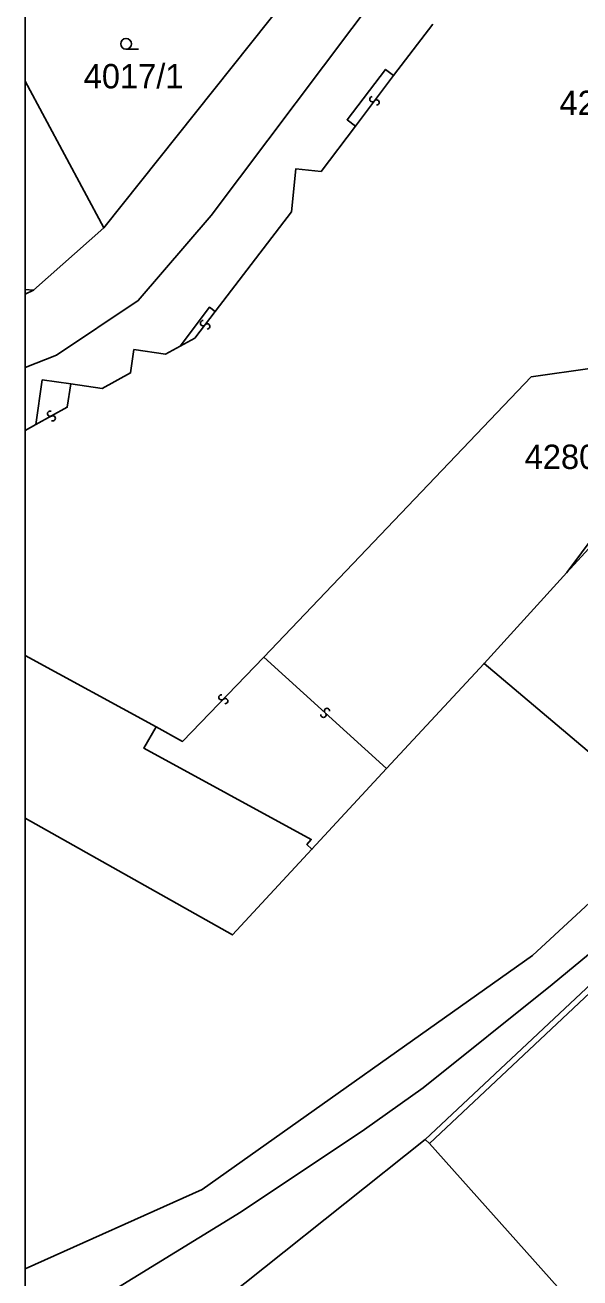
# Model space of a CAD drawing. Extents: x -598233 to -596890, y -1157848 to -1156431.
# Drawn here: x -598232.9 to -598194.2, y -1156969.1 to -1156881.8 of the extents above; entities that cross this region are included whole.
import ezdxf

# ---------------------------------------------------------------- set-up
doc = ezdxf.new("R2010")
doc.units = 0
for name, color, linetype in [('Level 1', 7, 'Continuous'), ('Level 13', 7, 'Continuous'), ('Level 3', 7, 'Continuous'), ('Level 4', 7, 'Continuous'), ('Level 5', 7, 'Continuous'), ('Level 57', 7, 'Continuous'), ('Level 60', 7, 'Continuous'), ('Vrstva 60', 7, 'Continuous'), ('zajmove_uzemi', 7, 'Continuous')]:
    doc.layers.add(name, color=color, linetype=linetype)

msp = doc.modelspace()

# ---------------------------------------------------------------- linework, layer by layer
at = {"layer": 'Level 1'}
for p, q in [((-598232.89, -1156885.695), (-598227.41, -1156895.92)), ((-598232.89, -1156900.213), (-598232.3, -1156900.27)), ((-598232.89, -1156900.551), (-598232.3, -1156900.27)), ((-598232.14, -1156909.64), (-598232.89, -1156910.044)), ((-598232.89, -1156925.714), (-598223.76, -1156930.7))]:
    msp.add_line(p, q, dxfattribs=at)
for points in [[(-598227.41, -1156895.92), (-598209.51, -1156873.47), (-598209.91, -1156869.66), (-598210.99, -1156868.62)], [(-598200.51, -1156871.31), (-598208.13, -1156879.38), (-598219.92, -1156895.06), (-598225, -1156901), (-598230.7, -1156904.8), (-598232.89, -1156905.647)], [(-598204.48, -1156881.73), (-598207.2, -1156885.32)], [(-598207.2, -1156885.32), (-598207.76, -1156884.89), (-598210.45, -1156888.39), (-598209.87, -1156888.84)], [(-598209.87, -1156888.84), (-598212.26, -1156892), (-598214.01, -1156891.81), (-598214.33, -1156894.81), (-598219.64, -1156901.76)], [(-598232.3, -1156900.27), (-598227.41, -1156895.92)], [(-598219.64, -1156901.76), (-598220.04, -1156901.46), (-598222.09, -1156904.17)], [(-598222.09, -1156904.17), (-598223.11, -1156904.73), (-598225.3, -1156904.41), (-598225.53, -1156906.04), (-598227.52, -1156907.12), (-598229.71, -1156906.8)], [(-598229.71, -1156906.8), (-598231.69, -1156906.52), (-598232.14, -1156909.64)], [(-598191.04, -1156914.46), (-598195.12, -1156919.95)], [(-598191.6, -1156916.09), (-598195.12, -1156919.95)], [(-598200.9, -1156926.28), (-598195.12, -1156919.95)], [(-598200.9, -1156926.28), (-598207.69, -1156933.6)], [(-598200.9, -1156926.28), (-598191.02, -1156934.61)], [(-598223.76, -1156930.7), (-598224.62, -1156932.18), (-598212.94, -1156938.54), (-598213.25, -1156938.9), (-598212.9, -1156939.22)], [(-598212.9, -1156939.22), (-598207.69, -1156933.6)], [(-598232.89, -1156937.052), (-598232.5, -1156937.26), (-598218.44, -1156945.19), (-598212.9, -1156939.22)], [(-598232.89, -1156968.469), (-598220.54, -1156962.94), (-598197.52, -1156946.62), (-598187.71, -1156937.56)], [(-598182.53, -1156938.39), (-598205.01, -1156959.45)], [(-598205.01, -1156959.45), (-598227.39, -1156977.29), (-598232.89, -1156981.238)], [(-598205.01, -1156959.45), (-598204.71, -1156959.73)], [(-598204.71, -1156959.73), (-598195.78, -1156969.72)]]:
    msp.add_lwpolyline(points, dxfattribs=at)
at = {"layer": 'Level 13'}
for centre, start, end in [((-598208.686, -1156886.967), 90.19159, 322.28959), ((-598208.394, -1156887.192), 269.97713, 142.56713), ((-598220.486, -1156902.567), 90.05946, 322.15745), ((-598220.194, -1156902.792), 269.845, 142.435), ((-598231.138, -1156908.878), 66.29388, 298.39188), ((-598230.962, -1156909.201), 246.07943, 118.66943), ((-598219.201, -1156928.641), 83.36563, 315.46363), ((-598218.938, -1156928.898), 263.15117, 135.74117), ((-598211.846, -1156929.584), 354.93132, 227.52132), ((-598212.095, -1156929.855), 175.14578, 47.24377)]:
    msp.add_arc(centre, 0.184, start, end, dxfattribs=at)
at = {"layer": 'Level 3'}
for points in [[(-598216.24, -1156925.84), (-598197.62, -1156906.31), (-598193.37, -1156905.71), (-598189.92, -1156903.86), (-598157.07, -1156860.47)], [(-598209.87, -1156888.84), (-598207.2, -1156885.32)], [(-598222.09, -1156904.17), (-598221.05, -1156903.61), (-598219.64, -1156901.76)], [(-598232.14, -1156909.64), (-598229.95, -1156908.43), (-598229.71, -1156906.8)], [(-598223.76, -1156930.7), (-598221.91, -1156931.71), (-598216.24, -1156925.84)], [(-598207.69, -1156933.6), (-598216.24, -1156925.84)], [(-598177.03, -1156929.81), (-598186.94, -1156941.05), (-598196.15, -1156948.64), (-598205.14, -1156955.85), (-598209.23, -1156958.75), (-598217.82, -1156964.49), (-598232.89, -1156973.723)], [(-598204.71, -1156959.73), (-598182.33, -1156938.71)]]:
    msp.add_lwpolyline(points, dxfattribs=at)
at = {"layer": 'Level 5'}
msp.add_line((-598225.85, -1156883.48), (-598224.975, -1156883.48), dxfattribs=at)
msp.add_circle((-598225.85, -1156883.105), 0.375, dxfattribs=at)
at = {"layer": 'Level 60'}
for points in [[(-598191.04, -1156914.46), (-598191.6, -1156916.09), (-598195.12, -1156919.95)], [(-598179.88, -1156927.01), (-598179.09, -1156927.87), (-598187.71, -1156937.56), (-598191.02, -1156934.61), (-598200.9, -1156926.28), (-598195.12, -1156919.95), (-598191.6, -1156916.09)], [(-598166.14, -1156946.6), (-598150.11, -1156971.99), (-598170.3, -1156992.5), (-598173.05, -1156995.3), (-598184.68, -1156981.99), (-598195.78, -1156969.72), (-598204.71, -1156959.73), (-598205.01, -1156959.45), (-598182.53, -1156938.39), (-598182.33, -1156938.71), (-598178.97, -1156942.36), (-598183.73, -1156946.69), (-598183.39, -1156947.03), (-598187.46, -1156950.75), (-598184.17, -1156954.37), (-598185.98, -1156956.09), (-598182.45, -1156959.89), (-598180.57, -1156958.17), (-598178.8, -1156960.21), (-598170.05, -1156952.22), (-598171.04, -1156951.09), (-598167.19, -1156947.57)]]:
    msp.add_lwpolyline(points, close=True, dxfattribs=at)
at = {"layer": 'Vrstva 60'}
for points in [[(-598232.89, -1156430.856), (-598232.89, -1157835.582)], [(-598227.39, -1156977.29), (-598205.01, -1156959.45), (-598182.53, -1156938.39), (-598179.13, -1156935.14), (-598176.46, -1156932.6), (-598175.47, -1156931.7), (-598176.4, -1156930.28), (-598162.94, -1156919.38), (-598157.65, -1156914.85), (-598152.41, -1156910.36), (-598151.58, -1156909.65), (-598142.18, -1156899.7), (-598128.28, -1156885.01), (-598120.66, -1156877.67)], [(-598208.13, -1156879.38), (-598219.92, -1156895.06), (-598225, -1156901), (-598230.7, -1156904.8), (-598232.89, -1156905.647), (-598232.89, -1156910.044), (-598232.14, -1156909.64), (-598231.69, -1156906.52), (-598229.71, -1156906.8), (-598227.52, -1156907.12), (-598225.53, -1156906.04), (-598225.3, -1156904.41), (-598223.11, -1156904.73), (-598222.09, -1156904.17), (-598220.04, -1156901.46), (-598219.64, -1156901.76), (-598214.33, -1156894.81), (-598214.01, -1156891.81), (-598212.26, -1156892), (-598209.87, -1156888.84), (-598210.45, -1156888.39), (-598207.76, -1156884.89), (-598207.2, -1156885.32), (-598204.48, -1156881.73)], [(-598132.02, -1156880.94), (-598145.06, -1156894.74), (-598155.93, -1156904.85), (-598166.9, -1156915.17), (-598179.88, -1156927.01), (-598179.09, -1156927.87), (-598187.71, -1156937.56), (-598197.52, -1156946.62), (-598220.54, -1156962.94), (-598232.89, -1156968.469), (-598232.89, -1156981.238)], [(-598204.48, -1156881.73), (-598207.2, -1156885.32), (-598207.76, -1156884.89), (-598210.45, -1156888.39), (-598209.87, -1156888.84), (-598212.26, -1156892), (-598214.01, -1156891.81), (-598214.33, -1156894.81), (-598219.64, -1156901.76), (-598220.04, -1156901.46), (-598222.09, -1156904.17), (-598223.11, -1156904.73), (-598225.3, -1156904.41), (-598225.53, -1156906.04), (-598227.52, -1156907.12), (-598229.71, -1156906.8), (-598231.69, -1156906.52), (-598232.14, -1156909.64), (-598232.89, -1156910.044), (-598232.89, -1156925.714), (-598223.76, -1156930.7), (-598224.62, -1156932.18), (-598212.94, -1156938.54), (-598213.25, -1156938.9), (-598212.9, -1156939.22), (-598207.69, -1156933.6), (-598200.9, -1156926.28), (-598195.12, -1156919.95), (-598191.04, -1156914.46)]]:
    msp.add_lwpolyline(points, dxfattribs=at)
for points in [[(-598232.89, -1156868.324), (-598232.89, -1156885.695), (-598227.41, -1156895.92), (-598209.51, -1156873.47), (-598209.91, -1156869.66), (-598210.99, -1156868.62), (-598222.7, -1156857.49)], [(-598232.89, -1156900.551), (-598232.89, -1156905.647), (-598230.7, -1156904.8), (-598225, -1156901), (-598219.92, -1156895.06), (-598208.13, -1156879.38), (-598200.51, -1156871.31), (-598204.87, -1156866.92), (-598205.37, -1156867.47), (-598206.25, -1156867.79), (-598208.34, -1156865.83), (-598210.99, -1156868.62), (-598209.91, -1156869.66), (-598209.51, -1156873.47), (-598227.41, -1156895.92), (-598232.3, -1156900.27)], [(-598232.89, -1156885.695), (-598232.89, -1156900.213), (-598232.3, -1156900.27), (-598227.41, -1156895.92)], [(-598232.89, -1156900.213), (-598232.89, -1156900.551), (-598232.3, -1156900.27)], [(-598232.89, -1156937.052), (-598232.5, -1156937.26), (-598218.44, -1156945.19), (-598212.9, -1156939.22), (-598213.25, -1156938.9), (-598212.94, -1156938.54), (-598224.62, -1156932.18), (-598223.76, -1156930.7), (-598232.89, -1156925.714)], [(-598232.89, -1156937.052), (-598232.89, -1156968.469), (-598220.54, -1156962.94), (-598197.52, -1156946.62), (-598187.71, -1156937.56), (-598191.02, -1156934.61), (-598200.9, -1156926.28), (-598207.69, -1156933.6), (-598212.9, -1156939.22), (-598218.44, -1156945.19), (-598232.5, -1156937.26)], [(-598232.89, -1156981.238), (-598232.89, -1156990.445), (-598232.73, -1156990.27), (-598232.58, -1156990.49), (-598229.91, -1156987.53), (-598228.72, -1156988.58), (-598226.12, -1156985.79), (-598224.87, -1156986.94), (-598222, -1156983.88), (-598218.13, -1156987.57), (-598220.52, -1156990.18), (-598219.05, -1156991.64), (-598217.86, -1156992.7), (-598216.37, -1156991.27), (-598216.01, -1156990.98), (-598195.78, -1156969.72), (-598204.71, -1156959.73), (-598205.01, -1156959.45), (-598227.39, -1156977.29)]]:
    msp.add_lwpolyline(points, close=True, dxfattribs=at)
at = {"layer": 'zajmove_uzemi'}
msp.add_lwpolyline([(-598232.89, -1156430.856), (-596890.462, -1156430.856), (-596890.462, -1157848.461), (-598232.89, -1157848.461)], close=True, dxfattribs=at)

# ---------------------------------------------------------------- texts
at = {"layer": 'Level 4'}
for s, p in [('4017/1', (-598228.801, -1156886.21)), ('4280/4', (-598195.64, -1156888.07))]:
    msp.add_text(s, height=1.7, dxfattribs=at).set_placement(p)
at = {"layer": 'Level 57'}
msp.add_text('4280/8', height=1.7, dxfattribs=at).set_placement((-598198.067, -1156912.73))

doc.saveas('drawing.dxf')
